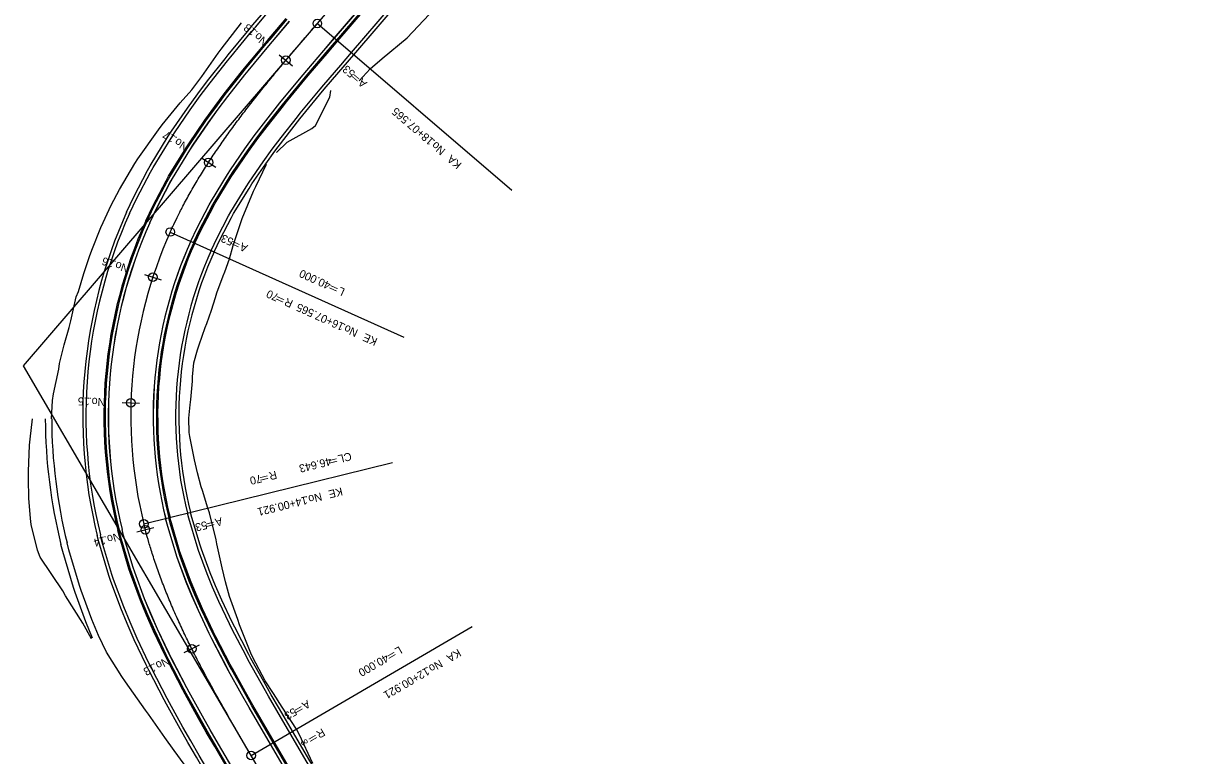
# Model space of a CAD drawing. Extents: x 46424 to 47578, y 10417 to 11548.
# Drawn here: x 46423.8 to 46607, y 10638.7 to 10753 of the extents above; entities that cross this region are included whole.
import ezdxf

# ---------------------------------------------------------------- set-up
doc = ezdxf.new("R2010")
doc.units = 0
for name, color, linetype in [('Default', 7, 'Continuous'), ('出典（地理院地図Vector）', 7, 'Continuous'), ('河川_人工水路(地下)（地理院地図Vector）', 7, 'Continuous'), ('現況_地形', 7, 'Continuous'), ('現況_地形_三角形', 7, 'Continuous'), ('現況_地形_三角形_頂点', 7, 'Continuous'), ('現況_地形_低い点', 7, 'Continuous'), ('現況_地形_単点標高', 7, 'Continuous'), ('現況_地形_等高線_マイナー', 7, 'Continuous'), ('等高線等深線_等高線_補助曲線通常部（地理院地図Vector）', 7, 'Continuous'), ('設計図面_測点 ラベル メジャー', 7, 'Continuous'), ('設計図面_測点 印 メジャー', 7, 'Continuous')]:
    doc.layers.add(name, color=color, linetype=linetype)

msp = doc.modelspace()

# ---------------------------------------------------------------- linework, layer by layer
at = {"layer": 'Default'}
for p, q in [((46423.8, 10699.52), (46606.99, 10913.06)), ((46469.69, 10753.01), (46500.05, 10726.97)), ((46464.78, 10747.26), (46464.78, 10747.26)), ((46452.72, 10731.32), (46452.72, 10731.32)), ((46446.73, 10720.44), (46446.73, 10720.44)), ((46446.73, 10720.44), (46483.2, 10704)), ((46446.73, 10720.44), (46483.2, 10704)), ((46444, 10713.38), (46444, 10713.38)), ((46440.58, 10693.75), (46440.58, 10693.75)), ((46442.6, 10674.84), (46481.43, 10684.46)), ((46442.6, 10674.84), (46481.43, 10684.46)), ((46442.6, 10674.84), (46442.6, 10674.84)), ((46442.83, 10673.94), (46442.83, 10673.94)), ((46459.34, 10638.67), (46493.88, 10658.84)), ((46450.08, 10655.34), (46450.08, 10655.34)), ((46459.34, 10638.67), (46459.34, 10638.67))]:
    msp.add_line(p, q, dxfattribs=at)
for centre in [(46469.69, 10753.01), (46464.78, 10747.26), (46452.72, 10731.32), (46446.73, 10720.44), (46444, 10713.38), (46440.58, 10693.75), (46442.6, 10674.84), (46442.83, 10673.94), (46450.08, 10655.34), (46459.34, 10638.67)]:
    msp.add_circle(centre, 0.675, dxfattribs=at)
msp.add_arc((46510.55, 10691.68), 70, 155.7426, 193.9208, dxfattribs=at)
for points in [[(46446.73, 10720.44), (46446.9, 10720.82), (46447.25, 10721.57), (46447.97, 10723.07), (46448.92, 10724.93), (46450.14, 10727.11), (46451.41, 10729.27), (46452.74, 10731.38), (46454.13, 10733.46), (46455.56, 10735.51), (46457.03, 10737.54), (46458.53, 10739.53), (46460.07, 10741.5), (46461.63, 10743.45), (46463.22, 10745.39), (46464.82, 10747.31), (46466.44, 10749.22), (46467.79, 10750.8), (46468.87, 10752.07), (46469.42, 10752.7), (46469.69, 10753.01)], [(46459.34, 10638.67), (46459.13, 10639.03), (46458.71, 10639.75), (46457.87, 10641.19), (46456.83, 10642.99), (46455.58, 10645.16), (46454.35, 10647.33), (46453.14, 10649.52), (46451.95, 10651.72), (46450.79, 10653.93), (46449.67, 10656.17), (46448.58, 10658.42), (46447.54, 10660.69), (46446.56, 10662.99), (46445.63, 10665.31), (46444.76, 10667.66), (46443.96, 10670.02), (46443.35, 10672.02), (46442.91, 10673.63), (46442.7, 10674.43), (46442.6, 10674.84)]]:
    msp.add_open_spline(points, degree=3, dxfattribs=at)
at = {"layer": '出典（地理院地図Vector）'}
for points in [[(46453.57, 10717.35), (46454.5, 10719.33), (46456.28, 10722.72), (46456.62, 10723.33), (46459.02, 10727.25), (46459.47, 10727.95), (46461.64, 10731.11), (46463.06, 10733.07), (46464.45, 10734.91), (46466.96, 10738.1), (46467.42, 10738.68), (46470.52, 10742.43), (46471.09, 10743.1), (46473.72, 10746.19), (46475.38, 10748.13), (46499.75, 10776.54)], [(46439.89, 10723.52), (46441.04, 10725.95), (46443.19, 10730.05), (46443.6, 10730.78), (46446.42, 10735.39), (46446.94, 10736.2), (46449.41, 10739.8), (46451.01, 10742), (46452.55, 10744.04), (46455.27, 10747.5), (46455.77, 10748.12), (46459.04, 10752.08), (46459.63, 10752.78), (46462.32, 10755.94)], [(46521.77, 10546.67), (46465.82, 10642.45), (46463.78, 10645.96), (46462.5, 10648.17), (46461.33, 10650.22), (46459.33, 10653.83), (46458.99, 10654.46), (46456.79, 10658.7), (46456.4, 10659.48), (46454.76, 10662.95), (46453.79, 10665.16), (46452.94, 10667.22), (46451.59, 10670.88), (46451.37, 10671.52), (46450.09, 10675.84), (46449.88, 10676.64)], [(46508.82, 10539.11), (46452.87, 10634.89), (46450.8, 10638.43), (46449.49, 10640.7), (46448.27, 10642.84), (46446.15, 10646.68), (46445.78, 10647.36), (46443.37, 10651.99), (46442.94, 10652.86), (46441.1, 10656.76), (46439.99, 10659.29), (46439, 10661.69), (46437.4, 10666.01), (46437.14, 10666.78), (46435.57, 10672.05), (46435.32, 10673.03)]]:
    msp.add_lwpolyline(points, dxfattribs=at)
for radius in [77.5, 62.5]:
    msp.add_arc((46510.55, 10691.68), radius, 155.7426, 193.9208, dxfattribs=at)
at = {"layer": '河川_人工水路(地下)（地理院地図Vector）'}
msp.add_arc((46510.55, 10691.68), 70, 155.7426, 193.9208, dxfattribs=at)
for points in [[(46446.73, 10720.44), (46446.9, 10720.82), (46447.25, 10721.57), (46447.97, 10723.07), (46448.92, 10724.93), (46450.14, 10727.11), (46451.41, 10729.27), (46452.74, 10731.38), (46454.13, 10733.46), (46455.56, 10735.51), (46457.03, 10737.54), (46458.53, 10739.53), (46460.07, 10741.5), (46461.63, 10743.45), (46463.22, 10745.39), (46464.82, 10747.31), (46466.44, 10749.22), (46467.79, 10750.8), (46468.87, 10752.07), (46469.42, 10752.7), (46469.69, 10753.01)], [(46459.34, 10638.67), (46459.13, 10639.03), (46458.71, 10639.75), (46457.87, 10641.19), (46456.83, 10642.99), (46455.58, 10645.16), (46454.35, 10647.33), (46453.14, 10649.52), (46451.95, 10651.72), (46450.79, 10653.93), (46449.67, 10656.17), (46448.58, 10658.42), (46447.54, 10660.69), (46446.56, 10662.99), (46445.63, 10665.31), (46444.76, 10667.66), (46443.96, 10670.02), (46443.35, 10672.02), (46442.91, 10673.63), (46442.7, 10674.43), (46442.6, 10674.84)]]:
    msp.add_open_spline(points, degree=3, dxfattribs=at)
at = {"layer": '現況_地形'}
for points in [[(46449.92, 10719), (46450.91, 10721.09), (46452.79, 10724.67), (46453.15, 10725.31), (46455.66, 10729.42), (46456.13, 10730.15), (46458.38, 10733.43), (46459.84, 10735.45), (46461.28, 10737.35), (46463.84, 10740.61), (46464.32, 10741.2), (46467.46, 10745), (46468.03, 10745.68), (46470.68, 10748.79), (46472.34, 10750.73), (46496.72, 10779.15)], [(46449.93, 10718.99), (46450.92, 10721.09), (46452.8, 10724.67), (46453.16, 10725.31), (46455.66, 10729.42), (46456.14, 10730.14), (46458.39, 10733.42), (46459.85, 10735.44), (46461.28, 10737.34), (46463.85, 10740.6), (46464.32, 10741.19), (46467.47, 10745), (46468.04, 10745.68), (46470.68, 10748.78), (46472.35, 10750.73), (46496.73, 10779.14)], [(46443.53, 10721.88), (46444.62, 10724.19), (46446.67, 10728.1), (46447.07, 10728.8), (46449.77, 10733.23), (46450.27, 10734), (46452.66, 10737.49), (46454.21, 10739.62), (46455.71, 10741.61), (46458.38, 10745), (46458.87, 10745.61), (46462.09, 10749.51), (46462.68, 10750.21), (46465.35, 10753.35)], [(46443.54, 10721.87), (46444.62, 10724.18), (46446.68, 10728.09), (46447.08, 10728.79), (46449.78, 10733.22), (46450.28, 10734), (46452.67, 10737.49), (46454.22, 10739.62), (46455.72, 10741.61), (46458.39, 10745), (46458.88, 10745.6), (46462.1, 10749.51), (46462.68, 10750.2), (46465.36, 10753.34)], [(46518.31, 10544.66), (46462.37, 10640.43), (46460.32, 10643.95), (46459.03, 10646.18), (46457.85, 10648.25), (46455.82, 10651.92), (46455.47, 10652.56), (46453.21, 10656.91), (46452.81, 10657.71), (46451.12, 10661.3), (46450.11, 10663.59), (46449.23, 10665.75), (46447.81, 10669.58), (46447.58, 10670.26), (46446.22, 10674.83), (46446, 10675.68)], [(46518.32, 10544.66), (46462.38, 10640.44), (46460.33, 10643.95), (46459.04, 10646.18), (46457.86, 10648.26), (46455.83, 10651.92), (46455.48, 10652.57), (46453.22, 10656.91), (46452.82, 10657.72), (46451.13, 10661.3), (46450.12, 10663.6), (46449.24, 10665.75), (46447.82, 10669.59), (46447.59, 10670.26), (46446.23, 10674.83), (46446.01, 10675.68)], [(46512.26, 10541.12), (46456.31, 10636.9), (46454.25, 10640.43), (46452.95, 10642.69), (46451.75, 10644.8), (46449.66, 10648.58), (46449.3, 10649.25), (46446.94, 10653.77), (46446.52, 10654.62), (46444.73, 10658.41), (46443.66, 10660.85), (46442.71, 10663.16), (46441.18, 10667.31), (46440.93, 10668.04), (46439.43, 10673.06), (46439.2, 10673.99)], [(46512.27, 10541.13), (46456.32, 10636.9), (46454.26, 10640.44), (46452.96, 10642.69), (46451.76, 10644.81), (46449.66, 10648.58), (46449.3, 10649.25), (46446.95, 10653.78), (46446.53, 10654.62), (46444.74, 10658.41), (46443.67, 10660.86), (46442.72, 10663.17), (46441.18, 10667.31), (46440.94, 10668.05), (46439.44, 10673.06), (46439.21, 10674)]]:
    msp.add_lwpolyline(points, dxfattribs=at)
for radius in [73.51, 73.5, 66.5, 66.49]:
    msp.add_arc((46510.55, 10691.68), radius, 155.7426, 193.9208, dxfattribs=at)
at = {"layer": '現況_地形_三角形'}
for points in [[(46476.2, 10744.06), (46477.93, 10745.94), (46479.83, 10747.52), (46483.7, 10750.79), (46487.16, 10754.41), (46490.41, 10758.2), (46493.07, 10762.51), (46495.53, 10766.99), (46498.41, 10771.11), (46501.45, 10775.08), (46504.5, 10779.05), (46507.57, 10782.99), (46508.94, 10784.75), (46510.64, 10786.91), (46513.74, 10790.8), (46516.69, 10794.47), (46516.85, 10794.67), (46520.03, 10798.47), (46523.26, 10802.22), (46524.65, 10803.95), (46526.35, 10806.08), (46529.46, 10809.92)], [(46428.2, 10691.27), (46428.31, 10694.11), (46428.5, 10695.18), (46429.34, 10699.02), (46429.45, 10699.9), (46430.17, 10702.82), (46430.95, 10705.54), (46431.2, 10706.56), (46432.05, 10710.3), (46432.37, 10711.13), (46433.23, 10713.96), (46434.1, 10716.61), (46434.45, 10717.59), (46435.87, 10721.14), (46436.22, 10721.95), (46437.48, 10724.61), (46438.77, 10727.06), (46441.21, 10731.16), (46441.67, 10731.88), (46444.87, 10736.39), (46445.47, 10737.16), (46448.29, 10740.6), (46450.1, 10742.67), (46451.66, 10744.72), (46454.18, 10748.38), (46454.66, 10749.02), (46457.83, 10753.1)], [(46469.01, 10637.45), (46466.87, 10642), (46466.41, 10642.79), (46464.22, 10646.21), (46462.83, 10648.35), (46461.54, 10650.33), (46459.63, 10653.99), (46459.32, 10654.64), (46457.55, 10659.08), (46457.25, 10659.9), (46455.98, 10663.5), (46455.34, 10665.82), (46454.82, 10667.97), (46454.02, 10671.71), (46453.9, 10672.36), (46452.87, 10676.57), (46452.61, 10677.32), (46451.74, 10680.04), (46451.56, 10680.66), (46450.98, 10682.81), (46450.49, 10684.85), (46450.33, 10685.62), (46449.79, 10688.48), (46449.68, 10689.13), (46449.6, 10691.37), (46449.83, 10693.47), (46449.95, 10694.26), (46450.19, 10697.14), (46450.17, 10697.8), (46450.38, 10700.02), (46450.99, 10702.05), (46451.23, 10702.8), (46452.19, 10705.53), (46452.43, 10706.14), (46453.16, 10708.22), (46453.77, 10710.2), (46454.01, 10710.93), (46454.98, 10713.6), (46455.22, 10714.21), (46455.97, 10716.27), (46456.54, 10718.32), (46457.72, 10721.91), (46457.97, 10722.56), (46459.72, 10726.8), (46460.06, 10727.56), (46461.75, 10731.03)], [(46434.4, 10656.92), (46433.06, 10659.34), (46430.36, 10663.6), (46429.92, 10664.38), (46426.41, 10669.65), (46426.01, 10670.73), (46424.99, 10674.75), (46424.89, 10675.67), (46424.64, 10678.89), (46424.56, 10681.9), (46424.56, 10683.03), (46424.76, 10687.16), (46424.84, 10688.09), (46425.22, 10691.25)], [(46434.6, 10657.01), (46433.56, 10659.53), (46431.87, 10664.12), (46431.59, 10664.94), (46429.92, 10670.56), (46429.65, 10671.63)], [(46468.38, 10608.14), (46465.72, 10612.37), (46463.56, 10615.55), (46457.3, 10624.83), (46454.61, 10629.05), (46451.91, 10633.26), (46448.91, 10637.33), (46447.34, 10639.47), (46445.88, 10641.49), (46443.3, 10645.13), (46442.84, 10645.77), (46439.74, 10650.18), (46439.18, 10651.01), (46436.78, 10654.81), (46435.52, 10657.4), (46434.49, 10659.9), (46432.81, 10664.44), (46432.54, 10665.25), (46430.88, 10670.82), (46430.62, 10671.87)]]:
    msp.add_lwpolyline(points, dxfattribs=at)
for radius in [83.35, 82.35]:
    msp.add_arc((46510.55, 10691.68), radius, 180.2857, 193.9208, dxfattribs=at)
at = {"layer": '現況_地形_三角形_頂点'}
msp.add_lwpolyline([(46463.31, 10732.88), (46465, 10734.49), (46468.84, 10736.59), (46469.42, 10737.07), (46471.62, 10741.51), (46471.78, 10742.53)], dxfattribs=at)
at = {"layer": '現況_地形_低い点'}
for points in [[(46450.37, 10718.79), (46451.35, 10720.87), (46453.23, 10724.43), (46453.59, 10725.07), (46456.08, 10729.15), (46456.55, 10729.87), (46458.78, 10733.14), (46460.25, 10735.15), (46461.67, 10737.04), (46464.23, 10740.3), (46464.7, 10740.88), (46467.84, 10744.68), (46468.42, 10745.36), (46471.06, 10748.47), (46472.72, 10750.41), (46497.1, 10778.82)], [(46443.08, 10722.08), (46444.18, 10724.4), (46446.25, 10728.34), (46446.64, 10729.04), (46449.36, 10733.49), (46449.87, 10734.27), (46452.26, 10737.78), (46453.82, 10739.91), (46455.32, 10741.91), (46458, 10745.31), (46458.49, 10745.92), (46461.72, 10749.83), (46462.3, 10750.52), (46464.98, 10753.67)], [(46518.75, 10544.91), (46462.8, 10640.69), (46460.75, 10644.2), (46459.47, 10646.42), (46458.29, 10648.5), (46456.26, 10652.16), (46455.91, 10652.8), (46453.66, 10657.13), (46453.26, 10657.94), (46451.57, 10661.51), (46450.57, 10663.79), (46449.69, 10665.93), (46448.28, 10669.74), (46448.05, 10670.42), (46446.7, 10674.96), (46446.49, 10675.8)], [(46511.84, 10540.87), (46455.89, 10636.65), (46453.83, 10640.19), (46452.53, 10642.44), (46451.32, 10644.56), (46449.23, 10648.34), (46448.86, 10649.01), (46446.5, 10653.56), (46446.08, 10654.4), (46444.29, 10658.21), (46443.21, 10660.66), (46442.25, 10662.98), (46440.71, 10667.15), (46440.46, 10667.89), (46438.96, 10672.93), (46438.72, 10673.87)]]:
    msp.add_lwpolyline(points, dxfattribs=at)
for radius in [74, 66]:
    msp.add_arc((46510.55, 10691.68), radius, 155.7426, 193.9208, dxfattribs=at)
at = {"layer": '現況_地形_単点標高'}
for points in [[(46450.56, 10718.71), (46451.53, 10720.79), (46453.4, 10724.33), (46453.76, 10724.97), (46456.24, 10729.04), (46456.71, 10729.76), (46458.95, 10733.02), (46460.41, 10735.03), (46461.83, 10736.92), (46464.39, 10740.17), (46464.86, 10740.76), (46468, 10744.55), (46468.57, 10745.23), (46471.21, 10748.34), (46472.87, 10750.28), (46497.25, 10778.69)], [(46453.11, 10717.56), (46454.05, 10719.55), (46455.84, 10722.96), (46456.19, 10723.58), (46458.6, 10727.52), (46459.05, 10728.22), (46461.23, 10731.4), (46462.66, 10733.37), (46464.05, 10735.22), (46466.57, 10738.42), (46467.03, 10739), (46470.14, 10742.75), (46470.71, 10743.43), (46473.34, 10746.51), (46475, 10748.46), (46499.37, 10776.87)], [(46440.35, 10723.31), (46441.48, 10725.73), (46443.63, 10729.8), (46444.04, 10730.53), (46446.84, 10735.12), (46447.36, 10735.92), (46449.82, 10739.51), (46451.41, 10741.7), (46452.94, 10743.74), (46455.66, 10747.19), (46456.16, 10747.81), (46459.42, 10751.76), (46460.01, 10752.46), (46462.7, 10755.62)], [(46442.9, 10722.16), (46444, 10724.49), (46446.07, 10728.44), (46446.47, 10729.14), (46449.19, 10733.6), (46449.7, 10734.38), (46452.1, 10737.89), (46453.66, 10740.03), (46455.16, 10742.03), (46457.84, 10745.44), (46458.33, 10746.05), (46461.57, 10749.96), (46462.15, 10750.65), (46464.83, 10753.8)], [(46518.92, 10545.01), (46462.97, 10640.79), (46460.92, 10644.3), (46459.64, 10646.52), (46458.46, 10648.59), (46456.43, 10652.25), (46456.09, 10652.9), (46453.84, 10657.22), (46453.44, 10658.02), (46451.76, 10661.59), (46450.75, 10663.87), (46449.88, 10666.01), (46448.47, 10669.81), (46448.24, 10670.48), (46446.89, 10675.01), (46446.68, 10675.85)], [(46521.34, 10546.42), (46465.39, 10642.2), (46463.35, 10645.71), (46462.07, 10647.92), (46460.9, 10649.97), (46458.89, 10653.59), (46458.55, 10654.22), (46456.34, 10658.47), (46455.95, 10659.26), (46454.31, 10662.74), (46453.33, 10664.96), (46452.48, 10667.04), (46451.12, 10670.72), (46450.9, 10671.36), (46449.6, 10675.72), (46449.4, 10676.52)], [(46509.25, 10539.36), (46453.3, 10635.14), (46451.24, 10638.68), (46449.92, 10640.95), (46448.71, 10643.09), (46446.59, 10646.91), (46446.22, 10647.59), (46443.82, 10652.21), (46443.39, 10653.08), (46441.55, 10656.97), (46440.45, 10659.49), (46439.47, 10661.88), (46437.87, 10666.18), (46437.62, 10666.94), (46436.06, 10672.17), (46435.81, 10673.15)], [(46511.67, 10540.77), (46455.72, 10636.55), (46453.66, 10640.08), (46452.35, 10642.34), (46451.15, 10644.47), (46449.05, 10648.25), (46448.69, 10648.92), (46446.33, 10653.47), (46445.9, 10654.32), (46444.1, 10658.12), (46443.02, 10660.58), (46442.07, 10662.91), (46440.52, 10667.08), (46440.27, 10667.83), (46438.77, 10672.88), (46438.53, 10673.83)]]:
    msp.add_lwpolyline(points, dxfattribs=at)
for radius in [77, 74.2, 65.8, 63]:
    msp.add_arc((46510.55, 10691.68), radius, 155.7426, 193.9208, dxfattribs=at)
at = {"layer": '現況_地形_等高線_マイナー'}
for points in [[(46450.39, 10718.78), (46451.37, 10720.86), (46453.24, 10724.42), (46453.6, 10725.06), (46456.09, 10729.14), (46456.56, 10729.86), (46458.8, 10733.13), (46460.26, 10735.14), (46461.69, 10737.03), (46464.25, 10740.28), (46464.72, 10740.87), (46467.86, 10744.67), (46468.43, 10745.35), (46471.07, 10748.45), (46472.74, 10750.4), (46497.11, 10778.81)], [(46443.06, 10722.09), (46444.16, 10724.41), (46446.23, 10728.35), (46446.63, 10729.05), (46449.34, 10733.5), (46449.85, 10734.28), (46452.25, 10737.79), (46453.8, 10739.93), (46455.31, 10741.92), (46457.98, 10745.32), (46458.47, 10745.93), (46461.7, 10749.84), (46462.29, 10750.54), (46464.96, 10753.68)], [(46518.76, 10544.92), (46462.82, 10640.7), (46460.77, 10644.21), (46459.48, 10646.43), (46458.3, 10648.51), (46456.28, 10652.17), (46455.93, 10652.81), (46453.68, 10657.14), (46453.28, 10657.94), (46451.59, 10661.51), (46450.59, 10663.8), (46449.71, 10665.94), (46448.3, 10669.75), (46448.07, 10670.42), (46446.72, 10674.96), (46446.5, 10675.8)], [(46511.82, 10540.86), (46455.87, 10636.64), (46453.81, 10640.18), (46452.51, 10642.43), (46451.3, 10644.55), (46449.21, 10648.34), (46448.85, 10649), (46446.49, 10653.55), (46446.07, 10654.39), (46444.27, 10658.2), (46443.19, 10660.65), (46442.24, 10662.97), (46440.69, 10667.14), (46440.44, 10667.88), (46438.94, 10672.93), (46438.7, 10673.87)]]:
    msp.add_lwpolyline(points, dxfattribs=at)
for radius in [74.02, 65.98]:
    msp.add_arc((46510.55, 10691.68), radius, 155.7426, 193.9208, dxfattribs=at)
at = {"layer": '等高線等深線_等高線_補助曲線通常部（地理院地図Vector）'}
msp.add_line((46545.38, 10491.38), (46423.8, 10699.52), dxfattribs=at)
msp.add_arc((46510.55, 10691.68), 70, 155.7426, 193.9208, dxfattribs=at)
msp.add_arc((46510.55, 10691.68), 70, 155.7426, 193.9208, dxfattribs=at)
for points in [[(46446.73, 10720.44), (46446.9, 10720.82), (46447.25, 10721.57), (46447.97, 10723.07), (46448.92, 10724.93), (46450.14, 10727.11), (46451.41, 10729.27), (46452.74, 10731.38), (46454.13, 10733.46), (46455.56, 10735.51), (46457.03, 10737.54), (46458.53, 10739.53), (46460.07, 10741.5), (46461.63, 10743.45), (46463.22, 10745.39), (46464.82, 10747.31), (46466.44, 10749.22), (46467.79, 10750.8), (46468.87, 10752.07), (46469.42, 10752.7), (46469.69, 10753.01)], [(46446.73, 10720.44), (46446.9, 10720.82), (46447.25, 10721.57), (46447.97, 10723.07), (46448.92, 10724.93), (46450.14, 10727.11), (46451.41, 10729.27), (46452.74, 10731.38), (46454.13, 10733.46), (46455.56, 10735.51), (46457.03, 10737.54), (46458.53, 10739.53), (46460.07, 10741.5), (46461.63, 10743.45), (46463.22, 10745.39), (46464.82, 10747.31), (46466.44, 10749.22), (46467.79, 10750.8), (46468.87, 10752.07), (46469.42, 10752.7), (46469.69, 10753.01)], [(46459.34, 10638.67), (46459.13, 10639.03), (46458.71, 10639.75), (46457.87, 10641.19), (46456.83, 10642.99), (46455.58, 10645.16), (46454.35, 10647.33), (46453.14, 10649.52), (46451.95, 10651.72), (46450.79, 10653.93), (46449.67, 10656.17), (46448.58, 10658.42), (46447.54, 10660.69), (46446.56, 10662.99), (46445.63, 10665.31), (46444.76, 10667.66), (46443.96, 10670.02), (46443.35, 10672.02), (46442.91, 10673.63), (46442.7, 10674.43), (46442.6, 10674.84)], [(46459.34, 10638.67), (46459.13, 10639.03), (46458.71, 10639.75), (46457.87, 10641.19), (46456.83, 10642.99), (46455.58, 10645.16), (46454.35, 10647.33), (46453.14, 10649.52), (46451.95, 10651.72), (46450.79, 10653.93), (46449.67, 10656.17), (46448.58, 10658.42), (46447.54, 10660.69), (46446.56, 10662.99), (46445.63, 10665.31), (46444.76, 10667.66), (46443.96, 10670.02), (46443.35, 10672.02), (46442.91, 10673.63), (46442.7, 10674.43), (46442.6, 10674.84)]]:
    msp.add_open_spline(points, degree=3, dxfattribs=at)
at = {"layer": '設計図面_測点 印 メジャー'}
for p, q in [((46463.75, 10748.12), (46465.81, 10746.39)), ((46451.58, 10732.05), (46453.85, 10730.59)), ((46442.71, 10713.8), (46445.28, 10712.97)), ((46439.23, 10693.79), (46441.93, 10693.71)), ((46441.52, 10673.6), (46444.14, 10674.29)), ((46448.87, 10654.74), (46451.29, 10655.95))]:
    msp.add_line(p, q, dxfattribs=at)

# ---------------------------------------------------------------- texts
at = {"layer": 'Default'}
for s, rotation, p in [('53', 139.3724, (46475.71, 10745.37)), ('A＝', 139.3724, (46477.56, 10743.79)), ('18+07.565', 139.3724, (46488.02, 10734.81)), ('\u3000No.', 139.3724, (46491.1, 10732.17)), ('KA', 139.3724, (46492.33, 10731.11)), ('53', 155.7426, (46456.71, 10719.36)), ('A＝', 155.7426, (46458.94, 10718.36)), ('40.000', 155.7426, (46471.89, 10712.53)), ('L＝', 155.7426, (46474.11, 10711.53)), ('70', 155.7426, (46463.79, 10710.69)), ('R＝', 155.7426, (46466.01, 10709.69)), ('16+07.565', 155.7426, (46474.01, 10706.09)), ('\u3000No.', 155.7426, (46477.71, 10704.42)), ('KE', 155.7426, (46479.19, 10703.75)), ('CL＝', 193.9208, (46474.87, 10686.05)), ('46.643', 193.9208, (46471.71, 10685.27)), ('70', 193.9208, (46460.84, 10682.58)), ('R＝', 193.9208, (46463.2, 10683.16)), ('KE', 193.9208, (46473.47, 10680.56)), ('14+00.921', 193.9208, (46467.95, 10679.19)), ('\u3000No.', 193.9208, (46471.9, 10680.17)), ('53', 193.9208, (46452.32, 10675.31)), ('A＝', 193.9208, (46454.69, 10675.9)), ('L＝', 210.291, (46482.48, 10655.8)), ('KA', 210.291, (46491.67, 10655.38)), ('40.000', 210.291, (46480.38, 10654.58)), ('\u3000No.', 210.291, (46490.27, 10654.56)), ('12+00.921', 210.291, (46486.76, 10652.51)), ('A＝', 210.291, (46468.12, 10647.41)), ('53', 210.291, (46466.01, 10646.18)), ('R＝∞', 210.291, (46470.43, 10642.97))]:
    msp.add_text(s, height=1.25, rotation=rotation, dxfattribs=at).set_placement(p)
at = {"layer": '設計図面_測点 ラベル メジャー'}
for s, rotation, p in [('18', 139.9579, (46460.26, 10751.88)), ('No.', 139.9579, (46462.12, 10750.31)), ('17', 147.1464, (46447.65, 10735.34)), ('No.', 147.1464, (46449.69, 10734.02)), ('16', 161.9345, (46438.07, 10715.98)), ('No.', 161.9345, (46440.39, 10715.22)), ('15', 178.3047, (46434.16, 10694.56)), ('No.', 178.3047, (46436.6, 10694.49)), ('No.', 194.6663, (46438.8, 10673.54)), ('14', 194.6663, (46436.45, 10672.92)), ('13', 206.5669, (46444.05, 10653.02)), ('No.', 206.5669, (46446.22, 10654.11))]:
    msp.add_text(s, height=1.25, rotation=rotation, dxfattribs=at).set_placement(p)

doc.saveas('drawing.dxf')
